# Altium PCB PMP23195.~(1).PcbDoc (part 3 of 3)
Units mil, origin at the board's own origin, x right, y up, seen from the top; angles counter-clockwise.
Board outline 3600 x 3000 mil, 4 copper layers (Top Layer, Signal Layer 1, Signal Layer 2, Bottom Layer), stack 39.6 mil thick; 143 components, 62 nets, 279 pads, 97 vias.
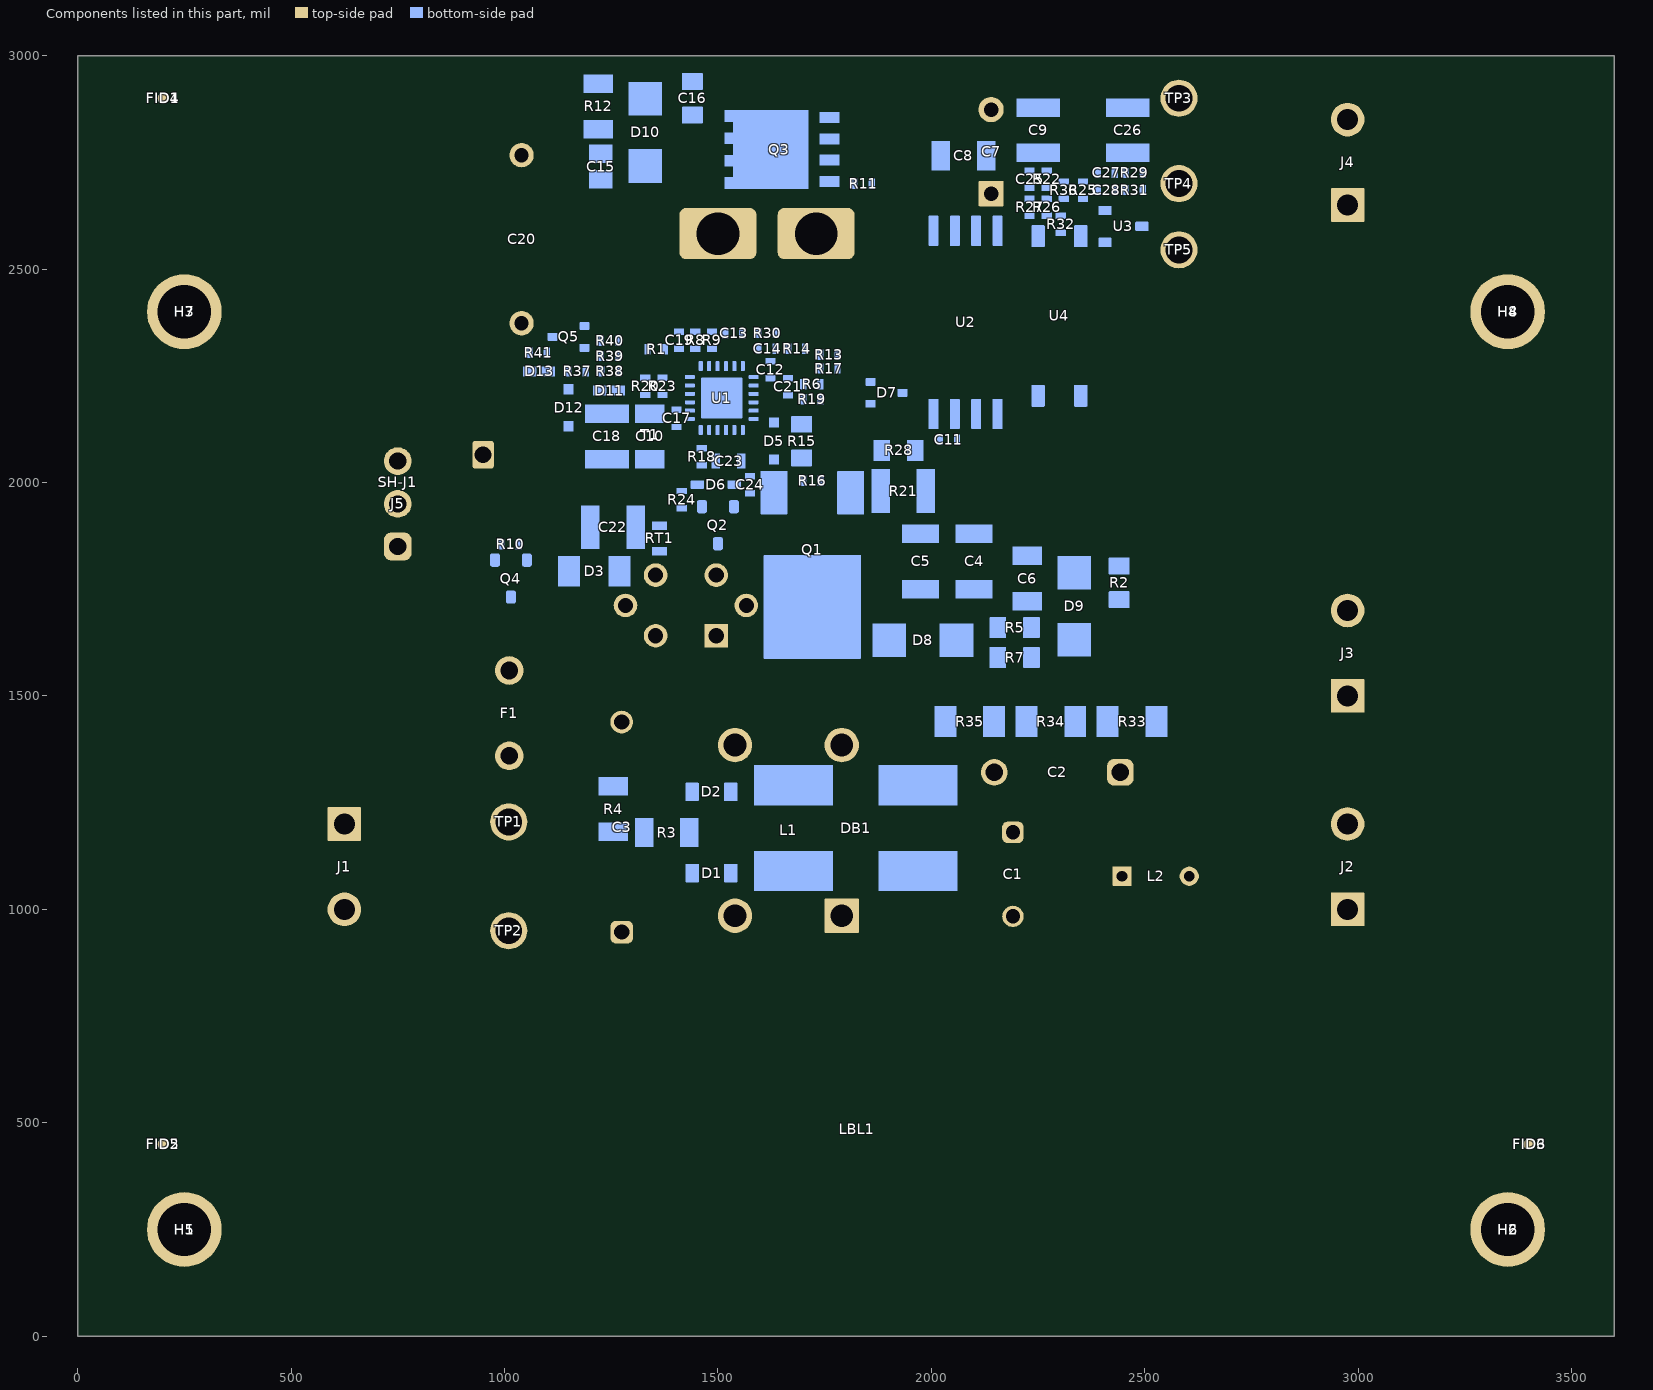
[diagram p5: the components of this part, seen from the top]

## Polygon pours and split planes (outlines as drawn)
GND_P on Bottom Layer "BOTTOM_LAYER_GND_P_P318" (solid, remove dead copper, pour order 318): 2592.05,2030 2592.05,1707.95 2619.98,1680.01 2645,1680.01 2645,2030
VOUT on Bottom Layer "BOTTOM_LAYER_VOUT_P314" (solid, remove dead copper, pour order 314): 2655,2820 2655,2630 2515,2630 2515,2755 2110,2755 2110,2820
Vbulk on Bottom Layer "BOTTOM_LAYER_VBULK_P308" (solid, remove dead copper, pour order 308): 1925,1815 1925,1765 2156,1765 2166,1775 2410.55,1775 2410.55,1890 2225,1890 2150,1815
GND_P on Bottom Layer "BOTTOM_LAYER_GND_P_P296" (solid, remove dead copper, pour order 296): 2525.51,1870 2598.51,1797 2634.79,1797 2635.32,1870 2635.32,2030 1950,2030 1950,1870
no net on Bottom Layer "BOTTOM_LAYER_NONET_P294" (solid, remove dead copper, pour order 294): 1052.4,2033.55
no net on Bottom Layer "BOTTOM_LAYER_NONET_P295" (solid, remove dead copper, pour order 295): 2050,2000
Vswn on Bottom Layer "BOTTOM_LAYER_VSWN_P297" (solid, remove dead copper, pour order 297): 1570,1830 1658,1830 1658,1750 1570,1750
Vswn on Bottom Layer "BOTTOM_LAYER_VSWN_P299" (solid, remove dead copper, pour order 299): 1570,1675 1665,1675 1665,1590 1570,1590
Vswn on Bottom Layer "BOTTOM_LAYER_VSWN_P300" (solid, remove dead copper, pour order 300): 1784.41,1830 1885,1830 1885,1680 1784.41,1680
NetC15_2 on Bottom Layer "Bottom Layer-NetC33_2" (solid, pour order 303): 1395,2660 1395,2900 1720,2900 1720,2660
GND_S on Bottom Layer "Bottom Layer-SGND" (solid, remove dead copper, pour order 307): 1000,2980 1000,2915 1795,2915 1795,2830 1795,2726.26 2050,2726.26 2050,2830 2655,2830 2655,2960 2635,2980
GND_P on Bottom Layer "BOTTOM_LAYER_GND_P_P306" (solid, remove dead copper, pour order 306): 1950,2150 1950,2020 2147.09,2020 2147.09,2150
QLSRC on Bottom Layer "BOTTOM_LAYER_QLSRC_P302" (solid, remove dead copper, pour order 302): 1770,2100 1770,1930 1890,1930 1890,2100
Vbulk on Bottom Layer "BOTTOM_LAYER_VBULK_P304" (solid, remove dead copper, pour order 304): 2512,1844 2645,1711 2645,1502 2397,1502 2397,1844
GND_P0 on Bottom Layer "BOTTOM_LAYER_GND_P0_P305" (solid, remove dead copper, pour order 305): 1900,1120 1900,880 2250,880 2250,1120
GND_S on Signal Layer 2 "Signal Layer 2-SGND" (solid, pour order 292): 949,2940.85 949,2790 1199,2540 2299,2540 2495,2540 2495,2725 2605,2835 2654,2835 2654,2915 2654,2965 2638.62,2980.38 988.08,2979.93
GND_P on Signal Layer 2 "SIGNAL_LAYER_2_GND_P_P293" (solid, remove dead copper, pour order 293): 1374.42,2365 1374.42,1541.23 2650,1541.23 2650,2143.51 2428.51,2365
GND_P on Signal Layer 2 "SIGNAL_LAYER_2_GND_P_P291" (solid, remove dead copper, pour order 291): 928,2390 928,1545.17 1765.07,1545.17 1769.08,2390
GND_P0 on Signal Layer 2 "SIGNAL_LAYER_2_GND_P0_P290" (solid, remove dead copper, pour order 290): 1900.33,1479.61 1900.33,880 2650,880 2650,1479.61
VOUT on Signal Layer 1 "Signal Layer 1-VN" (solid, pour order 288): 1155,2585 1185.01,2554.99 2589.99,2554.99 2655,2620 2655,2747 2432,2970 1155,2970
GND_P on Signal Layer 1 "SIGNAL_LAYER_1_GND_P_P289" (solid, remove dead copper, pour order 289): 1416.08,2301.91 1416.08,1540.41 2650,1540.41 2650,2301.91
GND_P on Signal Layer 1 "SIGNAL_LAYER_1_GND_P_P287" (solid, remove dead copper, pour order 287): 928,2389 928,1545.17 1781,1545.17 1781,2389
GND_P0 on Signal Layer 1 "SIGNAL_LAYER_1_GND_P0_P286" (solid, remove dead copper, pour order 286): 1900.33,1494 1900.33,880 2650,880 2650,1494
GND_P on Top Layer "TOP_LAYER_GND_P_P316" (solid, remove dead copper, pour order 316): 2550,2050 2550,1675 2645,1675 2645,2050
VOUT on Top Layer "Top Layer-VN" (solid, pour order 285): 1150,2975 1150,2730.42 1246.95,2660 1600,2660 1600,2555 2000,2555 2009.84,2564.84 2600.31,2565.31 2655,2620 2655,2745 2425,2975
GND_P on Top Layer "TOP_LAYER_GND_P_P283" (solid, remove dead copper, pour order 283): 1775,2226.84 1775,1850.06 2635.32,1849.92 2635.32,1964.68 2373.16,2226.84
GND_P on Top Layer "TOP_LAYER_GND_P_P284" (solid, remove dead copper, pour order 284): 940,2390 940,1887.57 1860,1887.57 1860,2390
Vbulk on Top Layer "TOP_LAYER_VBULK_P282" (solid, remove dead copper, pour order 282): 1579.94,1810 1579.94,1550 2450,1550 2450,1810
GND_P0 on Top Layer "TOP_LAYER_GND_P0_P280" (solid, remove dead copper, pour order 280): 1900,1495 1900,880 2250,880 2250,1495
Vbulk on Top Layer "TOP_LAYER_VBULK_P281" (solid, remove dead copper, pour order 281): 2225.7,1905 2225.7,1550 2450,1550 2450,1905

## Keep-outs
Top Layer:
  rectangle: 930.84,1654.42 961.35,1694.77
  lines w10: 1330,2245 1375,2245 ; 1387,2227.25 1435,2227.25
Signal Layer 1:
  rectangle: 930.84,1654.42 959.39,1694.77
  lines w10: 1335,2245 1375,2245 ; 1387,2227.25 1435,2227.25
Signal Layer 2:
  rectangle: 930.84,1654.42 958.4,1694.77
  lines w10: 1325,2245 1375,2245 ; 1387,2227.25 1435,2227.25
Bottom Layer:
  rectangle: 930.84,1654.42 961.35,1694.77
Keep-Out Layer:
  text ".Layer_Name" at 577,-858.49 h60

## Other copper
Top Layer:
  pour cut-out: 2380.55,2772.45 2389.97,2763.03 2547.64,2763.03 2570.31,2740.59 2547,2717.28 2529,2736.67 2358.7,2736.67 2336.23,2714.2 2295.79,2714.2 2295.79,2747.13 2318.85,2772.45
  pour cut-out: 1431.86,2328 1509,2328 1509,2259 1470,2259 1470,2284.16 1453.16,2301 1431.86,2301
  pour cut-out: 1285,2145 1205,2145 1205,2095 1235,2095 1285,2095
  pour cut-out: 1235,1930 1285,1930 1285,1845 1235,1845
  pour cut-out: 1320.63,1821.64
  pour cut-out: 1140.03,1639.65
  pour cut-out: 1318,1770.24 1318,1798 1338,1818 1370,1818 1389,1799 1389,1764.67 1372.33,1748 1337.55,1748
  region net GND_P: 1383.75,1760
  text ".Layer_Name" at 577,-858.49 h60
Signal Layer 1:
  pour cut-out: 2296.39,2714.17 2345,2714.17 2345,2758.48 2296.39,2758.51
  pour cut-out: 1432,2328.11 1509,2328.11 1509,2259 1470,2259 1470,2284.16 1453.16,2301 1432,2301
  pour cut-out: 1281.64,2150.76
  pour cut-out: 1281.64,2150.76
  pour cut-out: 1285,2145 1205,2145 1205,2095 1235,2095 1235,1845 1285,1845
  pour cut-out: 1317.52,1770.48 1317.52,1797.06 1338.46,1818 1369.54,1818 1389.37,1798.17 1389.37,1765.04 1371.59,1747.26 1337.93,1747.26
  pour cut-out: 1947,1673 1947,1576.66 1795.61,1576.66 1795.61,1673
  pour cut-out: 1886.5,1832.78 1886.5,1576.66 1568,1576.66 1568,1832.78
Signal Layer 2:
  pour cut-out: 1432,2328 1509,2328 1509,2259 1470,2259 1470,2283 1452,2301 1432,2301
  pour cut-out: 1235,1930 1285,1930 1285,1845 1235,1845
  pour cut-out: 1285,2145 1205,2145 1205,2095 1235,2095 1285,2095
  pour cut-out: 1318,1770.17 1318,1797.54 1338.46,1818 1369.54,1818 1389.37,1798.17 1389.37,1763.56 1373.32,1747.5 1337.93,1747.5
  pour cut-out: 1947,1673 1947,1576.66 1795.61,1576.66 1795.61,1673
  pour cut-out: 1886.5,1832.78 1886.5,1576.66 1568,1576.66 1568,1832.78
Bottom Layer:
  text ".Layer_Name" at 577,-858.49 h60

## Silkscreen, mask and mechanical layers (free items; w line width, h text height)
Top Overlay:
  region: 2460,235 2160,235 2160,135 2460,135
  lines w6: 1107.26,897.53 1441.9,897.53 1441.9,1488.08 1107.26,1488.08 1107.25,897.53
  lines w7: 950,1650 950,1710
  lines w7.87: 1148.49,2393.06 1148.49,2459.5
  lines w10: 40,910 60,850 ; 40,2935 60,2995 ; 50,850 70,850 ; 50,2995 70,2995 ; 60,1647.58 60,850 ; 60,2197.42 60,2995 ; 80,910 60,850 ; 80,2935 60,2995 ; 645,1985 690,1960 ; 645,1985.83 645,2030 690,2050 ; 690,1850 645,1870 645,1917.69 690,1940 ; 915,740 915,760 ; 975,730 915,750 ; 975,770 915,750 ; 1520.08,750 915,750 ; 1937,1411 2652,1411 ; 1937,1412 1937,1772 ; 1937,1816 1937,2462 2652,2462 2652,1413 ; 1945,1412 1945,1772 ; 1945,1816 1945,2462 ; 1954,1412 1954,1772 ; 1954,1816 1954,2462 ; 1962,1412 1962,1772 ; 1962,1816 1962,2462 ; 1970,1412 1970,1772 ; 1970,1816 1970,2462 ; 2069.92,750 2675,750 ; 2135,1360 2135,1410 ; 2160,1360 2160,1410 ; 2430,1360 2430,1410 ; 2455,1360 2455,1410 ; 2615,730 2675,750 ; 2615,770 2675,750 ; 2675,740 2675,760 ; 3155,1000 3205,1000 ; 3155,1200 3205,1200 ; 3155,1500 3205,1500 ; 3155,1700 3205,1700 ; 3155,2650 3205,2650 ; 3155,2850 3205,2850 ; 3180,975 3180,1025 ; 3180,1475 3180,1525 ; 3180,2625 3180,2675
  lines w30: 2055.47,2956.27 cw(c2140,2775) 2224.52,2956.27 ; 2107.25,902.57 ccw(c2191.77,1083.83) 2276.3,902.57
  text "GND_S" at 2310,2915 h40
  text "DC Output" at 3190,2900 h90
  text "15V 4A" at 3270,2780 h90
  text "CAUTION" at 120,2710 h100
  text "B" at 1487,2660 h40
  text "A" at 1717,2660 h40
  text "VOUT" at 2350,2645 h40
  text "HOT SURFACE" at 125,2614.57 h100
  text "Jumper:" at 290,2105 h40
  text "3" at 820,2030.1 h40
  text "XCD DISABLED" at 168,2010 h40
  text "2" at 820,1931 h40
  text "XCD ENABLED" at 200,1850 h40
  text "1" at 824,1831 h40
  text "2145 (mil)" at 94.99,1657.58 h60 r90
  text "40VDC" at 3387,1497 h90 r90
  text "to 500VDC" at 3462,1437 h90 r90
  text "J3: DC Input" at 3292,1412 h90 r90
  text "+" at 2340,1270 h60
  text "LINE" at 307.73,1180 h40
  text "LINE" at 938.17,1089 h35
  text "NEUT" at 937.73,1030 h35
  text "NEUT" at 307.73,980 h40
  text "Output" at 3376,960 h90 r90
  text "Rectified-AC" at 3296,880 h90 r90
  text "J1: AC Input" at 250,820 h90
  text "90VAC to 264VAC" at 150,735 h90
  text "1760 (mil)" at 1530.08,715.01 h60
  text "50/60 Hz" at 295,650 h90
  text "DANGER HIGH VOLTAGE" at 2490,640 h100
  text "DANGER HIGH VOLTAGE" at 45,555 h100
  text "CAUTION READ USER GUIDE FIRST" at 1600,420 h108.27
  text "UCC28781EVM-053" at 1500,250 h120
  text "HVP053  Rev. B" at 1500,150 h90
  text ".Layer_Name" at 577,-858.49 h60
Bottom Overlay:
  lines w5: 1316,2389 1315.5,2292 1325,2262 ; 1402,1993 1432,1993 ; 1412.17,2075 1441.83,2075 ; 1588.78,2399 1597,2372 ; 1638.09,2287.18 1650,2295 1650,2360 1639.83,2376 ; 1667,2034 1677,1986 ; 1719,2249 1719,2351 ; 1775.98,2318.91 1803,2340 ; 1790,2281 1814,2304 ; 2287,2678 2298.88,2739 ; 2289,2729 2316.67,2757 ; 2300.5,2569 2316.78,2548 2383,2548 2399.37,2529 ; 2329,2706.59 2351.39,2759 ; 2370,2713 2383,2750.05 2383,2836 ; 2395,2745 2395,2910 ; 2510,2725 2535,2745 ; 2511,2679 2530,2661
  lines w7: 1422,2265 1422,2284 ; 1422,2285 1442,2285
  lines w7.87: 1613.91,1351.81 1750,1352
  lines w8: 2355,1320 2385,1320 ; 2370,1305 2370,1335
  lines w10: 3035,1000 3085,1000 ; 3035,1200 3085,1200 ; 3035,1500 3085,1500 ; 3035,1700 3085,1700 ; 3035,2650 3085,2650 ; 3035,2850 3085,2850 ; 3060,975 3060,1025 ; 3060,1475 3060,1525 ; 3060,2625 3060,2675
  text "GND_S" at 2930,2780 h40
  text "CAUTION" at 801,2659 h100
  text "VOUT" at 2915,2580 h40
  text "HOT SURFACE" at 799,2568 h100
  text "B" at 1387,2560 h40
  text "A" at 1870,2560 h40
  text "CAUTION" at 3400,2100 h100
  text "HOT SURFACE" at 3405,2010 h100
  text "GND_P" at 2930,1630 h40
  text "Vbulk" at 2920,1430 h40
  text "DANGER" at 774,1372 h100
  text "HIGH VOLTAGE" at 773,1286 h100
  text "L" at 1111,1169 h100
  text "TP1" at 1110,1110 h72.83
  text "TP2" at 1110,1000 h72.83
  text "N" at 1120,916 h100
  text "DANGER" at 3500,850 h100
  text "HIGH VOLTAGE" at 3500,750 h100
  text "UCC28781EVM-053" at 3065,450 h108.27
  text "CAUTION" at 1405,260 h108.27
  text "READ USER GUIDE FIRST" at 1800,170 h108.27
  text ".Layer_Name" at 577,-858.49 h60
Top Paste:
  text ".Layer_Name" at 577,-858.49 h60
Bottom Paste:
  text ".Layer_Name" at 577,-858.49 h60
Top Solder:
  text ".Layer_Name" at 577,-858.49 h60
  text ".Layer_Name" at 577,-858.49 h60
Bottom Solder:
  text ".Layer_Name" at 577,-858.49 h60
Drill Guide:
  text ".Layer_Name" at 577,-858.49 h60
M1 Board Outline:
  drawing of 344 lines, arcs and shapes, not listed
  text ".Layer_Name" at 577,-858.49 h60
M2 Board Dimensions:
  rectangle: 125,-400 500,-275
  rectangle: 0,-275 125,-150
  lines w7: 0,-275 1000,-275 ; 125,-400 125,-150 ; 250,-400 250,-150 ; 500,-400 500,-150 ; 750,-400 750,-150 ; 0,-400 0,-150 1000,-150 1000,-400 0,-400
  text ".Layer_Name" at 577,-858.49 h60
M3 3D STEP Top:
  text ".Layer_Name" at 577,-858.49 h60
M4 3D STEP Bottom:
  text ".Layer_Name" at 577,-858.49 h60
M5 Assembly Top:
  lines w10: -292,-930.17 6308,-930.17 ; -292,-726.83 6310,-726.83 ; -292,-523.5 -292,-1133.5 3713,-1133.5 6310,-1133.5 6310,-523.5 -291.5,-523.5 -291.5,-1133.5 1284,-1133.5 ; 2173,-1133.5 2173,-523.5 ; 3440,-726.83 3440,-523.5 ; 4280,-726.83 4280,-523.5 ; 4902,-1140 4902,-937.17
  text "COMPONENTS MARKED 'DNP' SHOULD NOT BE POPULATED." at 1153.5,-318.5 h60
  text "ASSEMBLY VARIANT:" at 1153,-434 h60
  text ".VariantName" at 2189,-434 h60
  text "PCB VIEWED FROM TOP SIDE" at -228.5,-655.67 h60
  text "BOARD #:" at 2248,-655.67 h60
  text ".PRJ_Number" at 2793.5,-655.67 h60
  text "REV:" at 3638,-655.67 h60
  text ".PCB_Rev" at 3929.5,-655.67 h60
  text "SVN REV:" at 4476,-655.67 h60
  text ".VersionControl_RevNumber" at 4982,-655.67 h60
  text "TID #:" at 2248,-859 h60
  text ".TID" at 2793.5,-859 h60
  text "PLOT NAME =" at -228.5,-1064.34 h60
  text ".plot_File_Name" at 577,-1064.34 h60
  text "GENERATED    :" at 2250,-1064.34 h60
  text ".Print_Date" at 3119.5,-1064.34 h60
  text ".Print_Time" at 3848.5,-1064.34 h60
  text "TEXAS INSTRUMENTS" at 5113,-1064.34 h60
M6 Assembly Bottom:
  lines w10: -292.5,-727.33 6309.5,-727.33 ; -290.5,-930.67 6309.5,-930.67 ; 1115.5,-1140.5 1115.5,-937.67 ; 1737.5,-727.33 1737.5,-524 ; 2577.5,-727.33 2577.5,-524 ; 3844.5,-1134 3844.5,-524 ; 4733.5,-1134 6309,-1134 6309,-524 -292.5,-524 -292.5,-1134 2304.5,-1134 6309.5,-1134 6309.5,-524
  text "COMPONENTS MARKED 'DNP' SHOULD NOT BE POPULATED." at 6102,-318 h60
  text ".VariantName" at 5058,-434 h60
  text "ASSEMBLY VARIANT:" at 6097,-434 h60
  text ".VersionControl_RevNumber" at 1035.5,-656.17 h60
  text "SVN REV:" at 1541.5,-656.17 h60
  text ".PCB_Rev" at 2088,-656.17 h60
  text "REV:" at 2379.5,-656.17 h60
  text ".PRJ_Number" at 3224,-656.17 h60
  text "BOARD #:" at 3769.5,-656.17 h60
  text "PCB VIEWED FROM BOTTOM SIDE" at 6246,-656.17 h60
  text ".TID" at 3224,-859.5 h60
  text "TID #:" at 3769.5,-859.5 h60
  text "TEXAS INSTRUMENTS" at 904.5,-1064.84 h60
  text ".Print_Time" at 2169,-1064.84 h60
  text ".Print_Date" at 2898,-1064.84 h60
  text "GENERATED    :" at 3767.5,-1064.84 h60
  text ".plot_File_Name" at 5440.5,-1064.84 h60
  text "PLOT NAME =" at 6246,-1064.84 h60
M9 Title Sheet:
  drawing of 57 lines, arcs and shapes, not listed
  text "1" at 739.84,8036.5 h70
  text "2" at 3235.5,8036.5 h70
  text "3" at 5724.84,8036.5 h70
  text "4" at 8231.51,8036.5 h70
  text "5" at 10730.5,8036.5 h70
  text "6" at 13235.5,8036.5 h70
  text "A" at -416.5,6893.5 h70
  text "A" at 14383.5,6893.5 h70
  text "B" at -416.5,4513.5 h70
  text "B" at 14383.5,4513.5 h70
  text "C" at -416.5,2138.5 h70
  text "C" at 14383.5,2138.5 h70
  text "PROJECT TITLE:" at 11343.5,277.5 h45
  text ".PRJ_Title" at 11393.5,144.17 h70
  text "DESIGNED FOR:" at 11343.5,-23.5 h45
  text ".PRJ_Customer" at 11393.5,-163.5 h70
  text "D" at -416.5,-231.5 h70
  text "D" at 14383.5,-231.5 h70
  text "FILE NAME:" at 11343.5,-323.5 h45
  text ".PCB_File_Name_No_Path" at 11393.5,-443.5 h70
  text "Texas Instruments (TI) and/or its licensors do not warrant the accuracy or completeness of this specification" at 6374,-605.34 h45
  text "ENGINEER:" at 11343.5,-613.5 h45
  text "LAYOUT BY:" at 12848.5,-613.5 h45
  text "or any information contained therein. TI and/or its licensors do not warrant that this design will meet" at 6329.01,-718 h45
  text ".PRJ_Engineer" at 11393.5,-768.49 h70
  text ".PCB_Layout" at 12899,-768.49 h70
  text "the specifications, will be suitable for your application or fit for any particular purpose, or will operate in" at 6329.01,-830.67 h45
  text ".Layer_Name" at 577,-858.49 h60
  text "ALTIUM DESIGNER VERSION:" at 12848.5,-923.5 h45
  text "an implementation. TI and/or its licensors do not warrant that the design is production worthy. You should" at 6329.01,-943.33 h45
  text "completely validate and test your design implementation to confirm the system functionality for your application." at 6374,-1056 h45
  text ".print_Scale" at 11393.5,-1056.83 h70
  text ".Application_BuildNumber" at 12899,-1056.83 h70
  text "1" at 739.84,-1263.5 h70
  text "2" at 3235.5,-1263.5 h70
  text "3" at 5724.84,-1263.5 h70
  text "4" at 8231.51,-1263.5 h70
  text "5" at 10730.5,-1263.5 h70
  text "6" at 13235.5,-1263.5 h70
M10 Fab Notes:
  drawing of 189 lines, arcs and shapes, not listed
  text "DESIGN INFORMATION" at 12382.02,6356.17 h60
  text "MIN. TRACK WIDTH:" at 11737.46,6224.05 h60
  text "8" at 12833.7,6224.05 h60
  text "MIL" at 12988.46,6224.05 h60
  text "MIN. CLEARANCE:" at 11737.46,6099.92 h60
  text "0.2" at 12773.7,6099.93 h60
  text "mm" at 12988.46,6099.92 h60
  text "MIN. VIA PAD SIZE:" at 11737.46,5975.8 h60
  text "24" at 12803.71,5975.8 h60
  text "MIL" at 12988.46,5975.8 h60
  text "0.05mm (2MIL)" at 12432.46,5845.9 h60
  text "MINIMUM ANNULAR RING" at 11408.23,5837.67 h60
  text "EXTERNAL" at 13140.46,5837.67 h60
  text "PER" at 11608.23,5727.55 h60
  text "IPC-D-275 CLASS 2 LEVEL C" at 11828.23,5727.54 h60
  text "MIL, HOLES" at 13316.46,5627.07 h60
  text "+/-" at 12924,5618.48 h60
  text "+/-" at 13778,5618.48 h60
  text "REGISTRATION TOLERANCES:" at 11408.23,5617.42 h60
  text "METAL" at 12608,5617.42 h60
  text "5" at 13184.2,5617.42 h60
  text "3" at 14017.2,5617.42 h60
  text "MIL" at 14133.46,5617.42 h60
  text "HOLE SIZE TOLERANCE (UNLESS OTHERWISE SPECIFIED):" at 11408.23,5519.1 h60
  text "+/-" at 13778,5516.23 h60
  text "3" at 14017.2,5515.17 h60
  text "MIL" at 14133.46,5515.17 h60
  text "MATERIAL:" at 11333.46,5377.52 h60
  text "FR-4 High Tg" at 12319.9,5249 h60
  text "X" at 12175.46,5241.01 h60
  text "FR-408" at 11754.46,5236.49 h60
  text "OTHER" at 13242.46,5236.49 h60
  text "40.4 MIL (1.0mm) +/-10%" at 12074.56,5093.46 h60
  text "X" at 11955,5090 h60
  text "40MIL" at 13725,5086 h72
  text "THICKNESS:" at 11408.23,5085.24 h60
  text "OTHER" at 13359.46,5085.24 h60
  text "TOLERANCE:" at 11408.23,4946.92 h60
  text "X" at 12256.46,4946.92 h60
  text "ANSI IPC-6012 TYPE 3 CLASS 2" at 12434.48,4946.92 h60
  text "OTHER +/-" at 12434.46,4802.73 h60
  text "BOW & TWIST:" at 11408.23,4657.54 h60
  text "X" at 12256.46,4657.54 h60
  text "ANSI IPC-6012 TYPE 3 CLASS 2" at 12434.48,4657.54 h60
  text "OTHER +/-" at 12434.46,4510.85 h60
  text "DRILLING:" at 11333.46,4380.23 h60
  text "NC_DRILL FILES" at 13094.46,4275.04 h60
  text "REFERENCE:" at 11408.23,4271.1 h60
  text "X" at 12065.46,4271.01 h60
  text "AS SHOWN" at 12243.46,4271.1 h60
  text "X" at 12966.46,4271.1 h60
  text "OTHER" at 13392.46,4128.85 h60
  text "PTH COPPER THICKNESS:" at 11407.91,4125.32 h60
  text "X" at 12547.14,4125.32 h60
  text "20-30 um" at 12675.14,4125.32 h60
  text "BOARD FINISH:" at 11333.46,3977.73 h60
  text "SILKSCREEN:" at 11488.68,3867.6 h60
  text "X" at 12446.46,3867.6 h60
  text "TOP" at 12563.46,3867.6 h60
  text "X" at 12956.46,3867.6 h60
  text "BOTTOM" at 13074.46,3867.6 h60
  text "SILKSCREEN COLOR:" at 11488.68,3712.41 h60
  text "X" at 12445.46,3712.41 h60
  text "WHITE" at 12563.46,3712.41 h60
  text "OTHER" at 13074.46,3712.41 h60
  text "X" at 12576.46,3568.96 h60
  text "GREEN" at 12694.46,3568.96 h60
  text "OTHER" at 13312.46,3568.96 h60
  text "SOLDER RESIST COLOR:" at 11488.68,3562.1 h60
  text "X" at 12576.46,3414.71 h60
  text "MATTE" at 12694.46,3414.71 h60
  text "SEMI-GLOSS" at 13312,3414.07 h60
  text "IMMERSION GOLD (ENIG)" at 12394.46,3241.94 h60
  text "ENEPIG" at 13732,3234.72 h60
  text "SURFACE FINISH:" at 11333.46,3233.72 h60
  text "X" at 12216.46,3233.72 h60
  text "IMM. TIN/SILVER OR EQUIV" at 11663,3096.4 h60
  text "OTHER" at 13094.46,3092.47 h60
  text "ARRAY/PANEL:" at 11333.46,2937.09 h60
  text "CUT AND TRIM PER M1 BOARD OUTLINE" at 12394.46,2928.87 h60
  text "N.C. ROUTE" at 12394.46,2792.9 h60
  text "X" at 13082.46,2792.9 h60
  text "V. SCORE" at 13260.46,2792.9 h60
  text "CERTIFICATION:" at 11333.46,2663.77 h60
  text "MATERIALS AND WORKMANSHIP FOR ALL PCBS" at 12058.46,2663.77 h60
  text "TO MEET OR EXCEED THE REQUIREMENTS OF:" at 12058.46,2569.71 h60
  text "X" at 11695.97,2441.08 h60
  text "ANSI IPC-A-600F CLASS ->" at 11823.96,2441.08 h60
  text "X" at 13471.97,2441.08 h60
  text "2" at 13581.96,2441.08 h60
  text "1" at 13266.96,2439.58 h60
  text "3" at 13935.96,2439.58 h60
  text "X" at 12507.97,2293.39 h60
  text "RoHS" at 12635.96,2293.39 h60
  text "OTHER" at 13280.36,2293.39 h60
  text "PER ORDER" at 13677.42,2293.39 h60
  text "ALL BOARDS MUST MEET OR EXCEED UL94-V0 REQUIREMENTS." at 11361,2139.57 h60
  text "PCB MUST BEAR THE UL94V-0 UL REGISTERED MATERIAL ID NUMBER" at 11361,2023.5 h60
  text "ADDITIONAL REQUIREMENTS:" at 11333.46,1854.08 h60
  text "MICROSECTION:" at 11408.23,1746.95 h60
  text "YES" at 12313.96,1746.95 h60
  text "REQUIRED" at 13175.46,1602.62 h60
  text "BARE BOARD ELEC. TEST:" at 11408.23,1599.76 h60
  text "NONE" at 12713.96,1599.76 h60
  text "X" at 13057.46,1599.76 h60
  text "PER ORDER" at 13767.46,1599.76 h60
  text "XX MIL VIAS REQUIRE NON-CONDUCTIVE FILL AND PLANARIZE" at 11576.38,1394.82 h59
  text "XX MIL VIAS REQUIRE CONDUCTIVE FILL AND PLANARIZE" at 11584.38,1290.84 h60
  text "OUTER XX MIL VIAS REQUIRE 50 OHM SINGLE-ENDED IMPEDANCE" at 11583.39,1127.46 h58
  text "LAYER 2 & 3 (INNER LAYERS) XX MIL WIDE, XX MIL SPACE / TRACES REQUIRE 100 OHM DIFFERENTIAL IMPEDANCE" at 11575.39,891.74 h60
  text ".Layer_Name" at 577,-858.49 h60
M11 Gerber Information:
  lines w10: -292,-930.17 6308,-930.17 ; -292,-726.83 6310,-726.83 ; -292,-523.5 -292,-1133.5 3713,-1133.5 6310,-1133.5 6310,-523.5 -291.5,-523.5 -291.5,-1133.5 1284,-1133.5 ; 2173,-1133.5 2173,-523.5 ; 3440,-726.83 3440,-523.5 ; 4280,-726.83 4280,-523.5 ; 4902,-1140 4902,-937.17
  text "ALL ARTWORK VIEWED FROM TOP SIDE" at -228.5,-655.67 h60
  text "BOARD #:" at 2248,-655.67 h60
  text ".PRJ_Number" at 2793.5,-655.67 h60
  text "REV:" at 3638,-655.67 h60
  text ".PCB_Rev" at 3929.5,-655.67 h60
  text "SVN REV:" at 4476,-655.67 h60
  text ".VersionControl_RevNumber" at 4982,-655.67 h60
  text "LAYER NAME =" at -228.5,-858.49 h60
  text "TID #:" at 2248,-859 h60
  text ".TID" at 2793.5,-859 h60
  text "PLOT NAME =" at -228.5,-1064.34 h60
  text ".plot_File_Name" at 577,-1064.34 h60
  text "GENERATED    :" at 2250,-1064.34 h60
  text ".Print_Date" at 3119.5,-1064.34 h60
  text ".Print_Time" at 3848.5,-1064.34 h60
  text "TEXAS INSTRUMENTS" at 5113,-1064.34 h60
M12 Stackup:
  drawing of 295 lines, arcs and shapes, not listed
  text "Layer" at 9781.2,7840 h60
  text "Name" at 10191.11,7840 h60
  text "Material" at 11130.85,7840 h60
  text "Thickness" at 11990.62,7840 h60
  text "Constant" at 12640.46,7840 h60
  text "Board Layer Stack" at 13210.32,7840 h60
  text "1" at 9781.2,7720 h60
  text "Top Overlay" at 10191.11,7720 h60
  text "2" at 9781.2,7600 h60
  text "Top Solder" at 10191.11,7600 h60
  text "Solder Resist" at 11130.85,7600 h60
  text "0.40mil" at 11990.62,7600 h60
  text "3.5" at 12640.46,7600 h60
  text "3" at 9781.2,7480 h60
  text "Top Layer" at 10191.11,7480 h60
  text "Copper" at 11130.85,7480 h60
  text "1.40mil" at 11990.62,7480 h60
  text "4" at 9781.2,7360 h60
  text "Dielectric 1" at 10191.11,7360 h60
  text "FR-4" at 11130.85,7360 h60
  text "8.00mil" at 11990.62,7360 h60
  text "4.2" at 12640.46,7360 h60
  text "5" at 9781.2,7240 h60
  text "Signal Layer 1" at 10191.11,7240 h60
  text "Copper" at 11130.85,7240 h60
  text "1.40mil" at 11990.62,7240 h60
  text "6" at 9781.2,7120 h60
  text "Dielectric 2" at 10191.11,7120 h60
  text "FR-4" at 11130.85,7120 h60
  text "18.00mil" at 11990.62,7120 h60
  text "4.2" at 12640.46,7120 h60
  text "7" at 9781.2,7000 h60
  text "Signal Layer 2" at 10191.11,7000 h60
  text "Copper" at 11130.85,7000 h60
  text "1.40mil" at 11990.62,7000 h60
  text "8" at 9781.2,6880 h60
  text "Dielectric 3" at 10191.11,6880 h60
  text "FR-4" at 11130.85,6880 h60
  text "8.00mil" at 11990.62,6880 h60
  text "4.2" at 12640.46,6880 h60
  text "9" at 9781.2,6760 h60
  text "Bottom Layer" at 10191.11,6760 h60
  text "Copper" at 11130.85,6760 h60
  text "1.40mil" at 11990.62,6760 h60
  text "10" at 9781.2,6640 h60
  text "Bottom Solder" at 10191.11,6640 h60
  text "Solder Resist" at 11130.85,6640 h60
  text "0.40mil" at 11990.62,6640 h60
  text "3.5" at 12640.46,6640 h60
  text "11" at 9781.2,6520 h60
  text "Bottom Overlay" at 10191.11,6520 h60
  text ".Layer_Name" at 577,-858.49 h60
M13 Component Bodies Top:
  text ".Layer_Name" at 577,-858.49 h60
M14 Component Bodies Bottom:
  text ".Layer_Name" at 577,-858.49 h60
M15 Courtyards Top:
  text ".Layer_Name" at 577,-858.49 h60
M16 Courtyards Bottom:
  text ".Layer_Name" at 577,-858.49 h60
Drill Drawing:
  circle w10: c5363.72,3324.47 r16.58
  circle w10: c5363.72,3324.47 r27.63
  circle w10: c5363.72,3075.83 r27.63
  lines w10: 5336.09,2302.28 5336.09,2316.1 5349.9,2329.91 5336.09,2343.72 5336.09,2357.54 5349.9,2357.54 5363.72,2343.72 5377.53,2357.54 5391.34,2357.54 5391.34,2343.72 5377.53,2329.91 5391.34,2316.1 5391.34,2302.28 5377.53,2302.28 5363.72,2316.1 5349.9,2302.28 5336.09,2302.28 ; 5336.09,2481.86 5391.34,2481.86 5363.72,2426.6 5336.09,2481.86 ; 5336.09,2564.74 5349.9,2564.74 5349.9,2550.92 5377.53,2550.92 5377.53,2564.74 5391.34,2564.74 5391.34,2592.36 5377.53,2592.36 5377.53,2606.18 5349.9,2606.18 5349.9,2592.36 5336.09,2592.36 5336.09,2564.74 ; 5336.09,2689.06 5349.9,2689.06 5363.72,2675.24 5377.53,2689.06 5391.34,2689.06 5377.53,2702.87 5391.34,2716.68 5377.53,2716.68 5363.72,2730.5 5349.9,2716.68 5336.09,2716.68 5349.9,2702.87 5336.09,2689.06 ; 5336.09,2799.56 5391.34,2799.56 5391.34,2854.82 5336.09,2854.82 5336.09,2799.56 ; 5336.09,3186.34 5349.9,3186.34 5349.9,3172.52 5377.53,3172.52 5377.53,3186.34 5391.34,3186.34 5391.34,3213.96 5377.53,3213.96 5377.53,3227.78 5349.9,3227.78 5349.9,3213.96 5336.09,3213.96 5336.09,3186.34 ; 5336.09,3448.79 5363.72,3421.16 5391.34,3448.79 5363.72,3476.42 5336.09,3448.79 ; 5336.09,3669.8 5363.72,3683.62 5391.34,3669.8 5377.53,3697.43 5391.34,3725.06 5363.72,3711.24 5336.09,3725.06 5349.9,3697.43 5336.09,3669.8 ; 5347.14,3191.86 5355.43,3191.86 5355.43,3183.57 5372.01,3183.57 5372.01,3191.86 5380.29,3191.86 5380.29,3208.44 5372.01,3208.44 5372.01,3216.73 5355.43,3216.73 5355.43,3208.44 5347.14,3208.44 5347.14,3191.86 ; 5347.14,3680.85 5363.72,3689.14 5380.29,3680.85 5372.01,3697.43 5380.29,3714.01 5363.72,3705.72 5347.14,3714.01 5355.43,3697.43 5347.14,3680.85
  lines w12: 5286,2264.99 8517.49,2264.99 ; 5286,3881.15 8517.49,3881.15 ; 5623.86,2140.67 5623.86,4005.47 ; 5955.86,2140.67 5955.86,4005.47 ; 6592.43,2140.67 6592.43,4005.47 ; 6851.57,2140.67 6851.57,4005.47 ; 7226.72,2140.67 7226.72,4005.47 ; 7951.05,2140.67 7951.05,4005.47 ; 5286,2140.67 8517.49,2140.67 8517.49,4005.47 5286,4005.47 5286,2140.67
  text "Symbol" at 5360.59,3918.44 h72
  text "Quantity" at 5661.16,3918.44 h72
  text "Finished Hole Size" at 5993.16,3918.44 h72
  text "Plated" at 6629.72,3918.44 h72
  text "Hole Type" at 6888.86,3918.44 h72
  text "Drill Layer Pair" at 7264.02,3918.44 h72
  text "Hole Tolerance" at 7988.35,3918.44 h72
  text "5" at 5661.16,3794.12 h60
  text "7.87mil (0.200mm)" at 5993.16,3794.12 h60
  text "PTH" at 6629.72,3794.12 h60
  text "Round" at 6888.86,3794.12 h60
  text "Top Layer - Bottom Layer" at 7264.02,3794.12 h60
  text "D" at 5335.31,3784.13 h55.25
  text "92" at 5661.16,3669.8 h60
  text "11.81mil (0.300mm)" at 5993.16,3669.8 h60
  text "PTH" at 6629.72,3669.8 h60
  text "Round" at 6888.86,3669.8 h60
  text "Top Layer - Bottom Layer" at 7264.02,3669.8 h60
  text "2" at 5661.16,3545.48 h60
  text "25.59mil (0.650mm)" at 5993.16,3545.48 h60
  text "PTH" at 6629.72,3545.48 h60
  text "Round" at 6888.86,3545.48 h60
  text "Top Layer - Bottom Layer" at 7264.02,3545.48 h60
  text "C" at 5335.31,3535.49 h55.25
  text "6" at 5661.16,3421.16 h60
  text "33.47mil (0.850mm)" at 5993.16,3421.16 h60
  text "PTH" at 6629.72,3421.16 h60
  text "Round" at 6888.86,3421.16 h60
  text "Top Layer - Bottom Layer" at 7264.02,3421.16 h60
  text "8" at 5661.16,3296.84 h60
  text "35.43mil (0.900mm)" at 5993.16,3296.84 h60
  text "PTH" at 6629.72,3296.84 h60
  text "Round" at 6888.86,3296.84 h60
  text "Top Layer - Bottom Layer" at 7264.02,3296.84 h60
  text "1" at 5661.16,3172.52 h60
  text "39.37mil (1.000mm)" at 5993.16,3172.52 h60
  text "PTH" at 6629.72,3172.52 h60
  text "Round" at 6888.86,3172.52 h60
  text "Top Layer - Bottom Layer" at 7264.02,3172.52 h60
  text "3" at 5661.16,3048.2 h60
  text "40.00mil (1.016mm)" at 5993.16,3048.2 h60
  text "PTH" at 6629.72,3048.2 h60
  text "Round" at 6888.86,3048.2 h60
  text "Top Layer - Bottom Layer" at 7264.02,3048.2 h60
  text "4" at 5661.16,2923.88 h60
  text "41.34mil (1.050mm)" at 5993.16,2923.88 h60
  text "PTH" at 6629.72,2923.88 h60
  text "Round" at 6888.86,2923.88 h60
  text "Top Layer - Bottom Layer" at 7264.02,2923.88 h60
  text "A" at 5335.31,2913.89 h55.25
  text "8" at 5661.16,2799.56 h60
  text "49.21mil (1.250mm)" at 5993.16,2799.56 h60
  text "PTH" at 6629.72,2799.56 h60
  text "Round" at 6888.86,2799.56 h60
  text "Top Layer - Bottom Layer" at 7264.02,2799.56 h60
  text "4" at 5661.16,2675.24 h60
  text "53.15mil (1.350mm)" at 5993.16,2675.24 h60
  text "PTH" at 6629.72,2675.24 h60
  text "Round" at 6888.86,2675.24 h60
  text "Top Layer - Bottom Layer" at 7264.02,2675.24 h60
  text "5" at 5661.16,2550.92 h60
  text "63.00mil (1.600mm)" at 5993.16,2550.92 h60
  text "PTH" at 6629.72,2550.92 h60
  text "Round" at 6888.86,2550.92 h60
  text "Top Layer - Bottom Layer" at 7264.02,2550.92 h60
  text "2" at 5661.16,2426.6 h60
  text "100.00mil (2.540mm)" at 5993.16,2426.6 h60
  text "PTH" at 6629.72,2426.6 h60
  text "Round" at 6888.86,2426.6 h60
  text "Top Layer - Bottom Layer" at 7264.02,2426.6 h60
  text "4" at 5661.16,2302.28 h60
  text "125.00mil (3.175mm)" at 5993.16,2302.28 h60
  text "PTH" at 6629.72,2302.28 h60
  text "Round" at 6888.86,2302.28 h60
  text "Top Layer - Bottom Layer" at 7264.02,2302.28 h60
  text "144 Total" at 5661.16,2177.96 h60
  text ".Layer_Name" at 577,-858.49 h60
Mechanical 17:
  text ".Layer_Name" at 577,-858.49 h60
Mechanical 18:
  text ".Layer_Name" at 577,-858.49 h60
Mechanical 19:
  text ".Layer_Name" at 577,-858.49 h60

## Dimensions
0,-400 to 1000,-400 on M2 Board Dimensions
